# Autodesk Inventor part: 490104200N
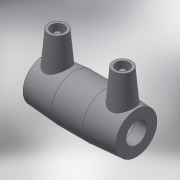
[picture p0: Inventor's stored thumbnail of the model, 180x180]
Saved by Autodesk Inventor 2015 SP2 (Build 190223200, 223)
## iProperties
Created: 2017-06
Part Number: 490104200N
Material: Generic
Description: PLASSON COUPLER 200-200
Document SubType Name: Modeling
Designer: KIM
Mass: 55.0731 g
Surface Area: 148.067 cm^2
Volume: 55.0731 cm^3
Density: 1 g/cm^3
Appearance: Default
Author: KIM
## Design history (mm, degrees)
derived "490104.ipt"
feature "Solid1::490104.ipt"
tag "TaggingFeature1"
body "Solid1"
other parameters: "d0" = 223, "d2" = 242, "d3" = 109, "d4" = 74.33333, "d5" = 217.8, "d8" = 168 deg, "d10" = 43.6, "d11" = 14.53333, "d13" = 223, "d14" = 17.6296, "d15" = 109, "d16" = 109, "d19" = 3.52592, "d20" = 168 deg, "d22" = 227.48, "d23" = 242, "d24" = 220.6556, "d25" = 135 deg, "d26" = 111.5, "d27" = 135 deg, "d29" = 126, "d30" = 14, "d31" = 78.05, "d34" = 5 deg, "d35" = 15, "d39" = 5 deg, "d41" = 4, "d42" = 14, "d43" = 0, "d45" = 4, "d46" = 14, "d47" = 0, "d48" = 3, "d49" = 0, "d50" = 3, "d51" = 0, "d52" = 31.61, "d53" = 7.9025, "L_" = 223, "L_1" = 109, "D_" = 242, "A_" = 126, "d_2" = 12
